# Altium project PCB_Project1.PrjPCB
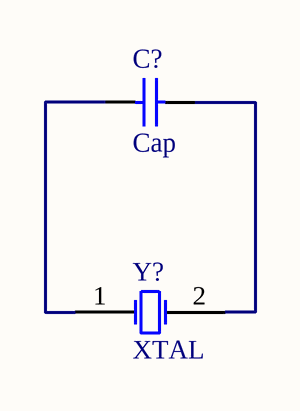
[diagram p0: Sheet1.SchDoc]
1 sheet, 2 parts. Net scope: global (net labels, ports and power ports of the same name join across sheets).
Board file: PCB1.PcbDoc

## Sheet Sheet1.SchDoc
size A4

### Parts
C?  Cap  [Capacitor]
Y?  XTAL  [BCY-W2/D3.1]

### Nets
NetC?_1: C?.1 Y?.1(OSC1)
NetC?_2: C?.2 Y?.2(OSC2)

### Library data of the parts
C? = Cap: Capacitor
Y? = XTAL: Crystal Oscillator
